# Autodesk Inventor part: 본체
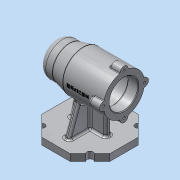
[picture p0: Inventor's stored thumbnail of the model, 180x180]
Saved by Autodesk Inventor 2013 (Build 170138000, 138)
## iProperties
Created: 2021-01
Part Number: 본체
Material: 알루미늄 6061
Document SubType Name: Modeling
Designer: Administrator
Density: 2.71 g/cm^3
Mass: 632.295 g
Surface Area: 613.785 cm^2
Volume: 233.319 cm^3
Author: Administrator
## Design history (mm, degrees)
sketch "스케치1"
  geometry: L1 (50, -20.711)-(20.711, -50); L2 (20.711, -50)-(-20.711, -50); L3 (-20.711, -50)-(-50, -20.711); L4 (-50, -20.711)-(-50, 20.711); L5 (-50, 20.711)-(-20.711, 50); L6 (-20.711, 50)-(20.711, 50); L7 (20.711, 50)-(50, 20.711); L8 (50, 20.711)-(50, -20.711); 3 further points
  constraints: 16 end point, 1 coincident, 1 horizontal alignment, 1 midpoint, 17 other
  dimensions: "d0" = 50 distance from line of L8 point (0, 0)
extrude "돌출1" new body sketch "스케치1" distance "d1" = 10; taper "d2" = 0 deg
sketch "스케치2"
  geometry: L1 (20.711, 0)-(-20.711, 0) reference; L2 (50, 75)-(-50, 75); L3 (-20.711, 0)-(-50, 0) reference; L4 (50, 0)-(20.711, 0) reference; L5 (50, 75)-(50, 100); L6 (50, 100)-(30, 100); L7 (30, 100)-(10, 105); L8 (10, 105)-(-50, 105); L9 (-50, 105)-(-50, 75); L10 (37, 75)-(37, 92.5); L11 (37, 92.5)-(19, 92.5); L12 (19, 92.5)-(19, 96); L13 (19, 96)-(7, 96); L14 (7, 96)-(7, 99); L15 (7, 99)-(-35, 99); L16 (-35, 99)-(-35, 96); L17 (-35, 96)-(-50, 96); 1 further point
  constraints: 28 end point, 8 parallel, 5 perpendicular, 2 point on line, 1 vertical alignment
  dimensions: "d3" = 100 distance of L2.start L2.end; "d5" = 75 distance from line of L4.start L2; "d6" = 20 distance of L5.end L6.end; "d7" = 60 distance of L7.end L8.end; "d8" = 50 diameter of L6 L2; "d9" = 60 diameter of L8 L2; "d10" = 15 distance of L16.end L17.end; "d11" = 42 distance of L14.end L15.end; "d12" = 12 distance of L12.end L13.end; "d13" = 18 distance of L10.end L11.end; "d14" = 35 diameter of L11 L2; "d15" = 42 diameter of L13 L2; "d16" = 48 diameter of L15 L2; "d17" = 42 diameter of L17 L2
revolve "회전1" sketch "스케치2" stored, may be unused: angle "d18" = 90 deg
sketch "스케치3"
  geometry: L1 (-20.711, 10)-(-50, 10) reference; L2 (50, 10)-(20.711, 10) reference; L3 (20.711, 10)-(-20.711, 10) reference; L4 (35, 10)-(19.606, 52.293); L5 (-19.606, 52.293)-(-35, 10); A1 r 30 centre (0, 75) between (19.606, 52.293) and (-19.606, 52.293) reference; 1 further point
  constraints: 4 end point, 2 point on circle, 2 point on line
  dimensions: "d19" = 15 distance of L2.start L4.start; "d20" = 15 distance of L5.end L1.end; "d21" = 110 deg angle of L1 L5; "d22" = 110 deg angle of L2 L4
extrude "돌출2" join sketch "스케치3" stored distance "d23" = 8; taper "d24" = 0 deg
sketch "스케치4"
  geometry: L1 (0, 4)-(27, 4); L2 (27, 4)-(27, -4); L3 (27, -4)-(0, -4); L4 (0, -4)-(0, 4); L5 (50, 20.711)-(50, -20.711) reference; 2 further points
  constraints: 8 end point, 2 parallel, 1 coincident, 1 horizontal, 1 midpoint, 1 perpendicular
  dimensions: "d25" = 8 distance of L1.end L2.end; "d27" = 23 distance between parallel lines of L5 L2
extrude "돌출3" join sketch "스케치4" stored distance "d28" = 8; taper "d29" = 0 deg
sketch "스케치5"
  geometry: L1 (10, 45)-(30, 50) reference; L2 (-50, 45)-(10, 45) reference; L3 (4, 10)-(4, 52.293) reference; L4 (20.711, 10)-(-20.711, 10) reference; L5 (50, 10)-(20.711, 10) reference; L6 (19.724, 47.431)-(27, 10); 1 further point
  constraints: 2 end point, 2 point on line
  dimensions: "d30" = 23 distance of L5.start L6.end; "d31" = 101 deg angle of L5 L6
feature "리브1" sketch "스케치5" dims "d32" = 1, "d33" = 8, "d34" = 0, "d35" = 0, "d36" = 1, "d37" = 1
sketch "스케치6"
  geometry: L1 (50, 20.711)-(50, -20.711) reference; L2 (50, -20.711)-(20.711, -50) reference; L3 (20.711, -50)-(-20.711, -50) reference; L4 (-20.711, -50)-(-50, -20.711) reference; L5 (-50, -20.711)-(-50, 20.711) reference; L6 (-50, 20.711)-(-20.711, 50) reference; L7 (-20.711, 50)-(20.711, 50) reference; L8 (20.711, 50)-(50, 20.711) reference; 5 further points
  constraints: 4 midpoint
hole "구멍1" sketch "스케치6" at (35.355, 35.355), (-35.355, 35.355), (-35.355, -35.355), (35.355, -35.355) diameter "d38" = 9; stored, may be unused: countersink angle "d42" = 90 deg, drill point angle "d44" = 118 deg; dims "d39" = 6, "d40" = 4, "d41" = 2, "d43" = 8
sketch "스케치7"
  geometry: C1 r 6 at (0, -30); C2 r 6 at (30, 0); C3 r 6 at (0, 30); C4 r 6 at (-30, 0); 2 further points
  constraints: 4 centre point, 2 vertical alignment, 10 other
  dimensions: "d47" = 360 deg dimension on point (0, 0) C1.centre (derived); "d49" = 12 diameter of C1
extrude "돌출4" join sketch "스케치7" distance "d50" = 16; taper "d51" = 0 deg
sketch "스케치8"
  geometry: C1 r 21 at (-30, 0) reference; A1 r 30 centre (-30, 0) between (-59.4, -5.97) and (-35.97, -29.4) reference; A2 r 6 centre (-30, -30) between (-35.97, -29.4) and (-24.03, -29.4) reference; A3 r 30 centre (-30, 0) between (-24.03, -29.4) and (-0.6, -5.97) reference; A4 r 6 centre (0, 0) between (-0.6, -5.97) and (-0.6, 5.97) reference; A5 r 30 centre (-30, 0) between (-0.6, 5.97) and (-24.03, 29.4) reference; A6 r 6 centre (-30, 30) between (-24.03, 29.4) and (-35.97, 29.4) reference; A7 r 30 centre (-30, 0) between (-35.97, 29.4) and (-59.4, 5.97) reference; A8 r 6 centre (-60, 0) between (-59.4, 5.97) and (-59.4, -5.97) reference; 1 further point
hole "구멍2" sketch "스케치8" at (-60, 0) diameter "d52" = 3.242; stored, may be unused: countersink angle "d56" = 90 deg, drill point angle "d58" = 118 deg; dims "d53" = 8, "d54" = 4, "d55" = 2, "d57" = 10
node "작업 평면1"
sketch "스케치9"
  geometry: L1 (-30, 100)-(-30, 50) reference; L2 (50, 104.4)-(50, 80.97) reference; 3 further points
  constraints: 1 horizontal alignment, 1 midpoint, 1 other
  dimensions: "d63" = 38 distance from line of L2 point (12, 75)
feature "엠보싱1" sketch "스케치9" dims "d0" = 50, "d3" = 100, "d5" = 75, "d6" = 20, "d7" = 60, "d8" = 50, "d9" = 60, "d10" = 15, "d11" = 42, "d12" = 12, "d13" = 18, "d14" = 35, "d15" = 42, "d16" = 48, "d17" = 42, "d64" = 0.5, "d65" = 0
chamfer "모따기1" distance "d66" = 1; stored, may be unused: second distance "d67" = 2, angle "d68" = 45 deg
fillet "모깎기1" dims "d69" = 3
sketch "스케치10"
  geometry: C1 r 17.5 at (0, 0) reference; C2 r 16 at (0, 0); 1 further point
  constraints: 1 centre point, 1 coincident
  dimensions: "d70" = 32 diameter of C2
extrude "돌출5" cut sketch "스케치10" distance "d72" = 4; taper "d73" = 0 deg
sketch "스케치11"
  geometry: C1 r 16 at (0, 0) reference; C2 r 10.5 at (0, 0); 1 further point
  constraints: 1 centre point, 1 coincident
  dimensions: "d74" = 21 diameter of C2
extrude "돌출6" cut sketch "스케치11" distance "d76" = 3; taper "d77" = 0 deg
fillet "모깎기2" dims "d78" = 10
fillet "모깎기3" dims "d79" = 3
fillet "모깎기4" dims "d80" = 0.3
fillet "모깎기5" dims "d81" = 3
fillet "모깎기6" dims "d82" = 1
fillet "모깎기7" dims "d83" = 3
fillet "모깎기8" dims "d84" = 3
fillet "모깎기9" dims "d85" = 3
node "솔리드1"
pattern_circular "원형 패턴1" dims angle "d60" = 360 deg
node "투영된 루프1"
node "투영된 루프2"
node "투영된 루프3"
node "투영된 루프4"
